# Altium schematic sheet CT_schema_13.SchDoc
size 390 x 385 mm
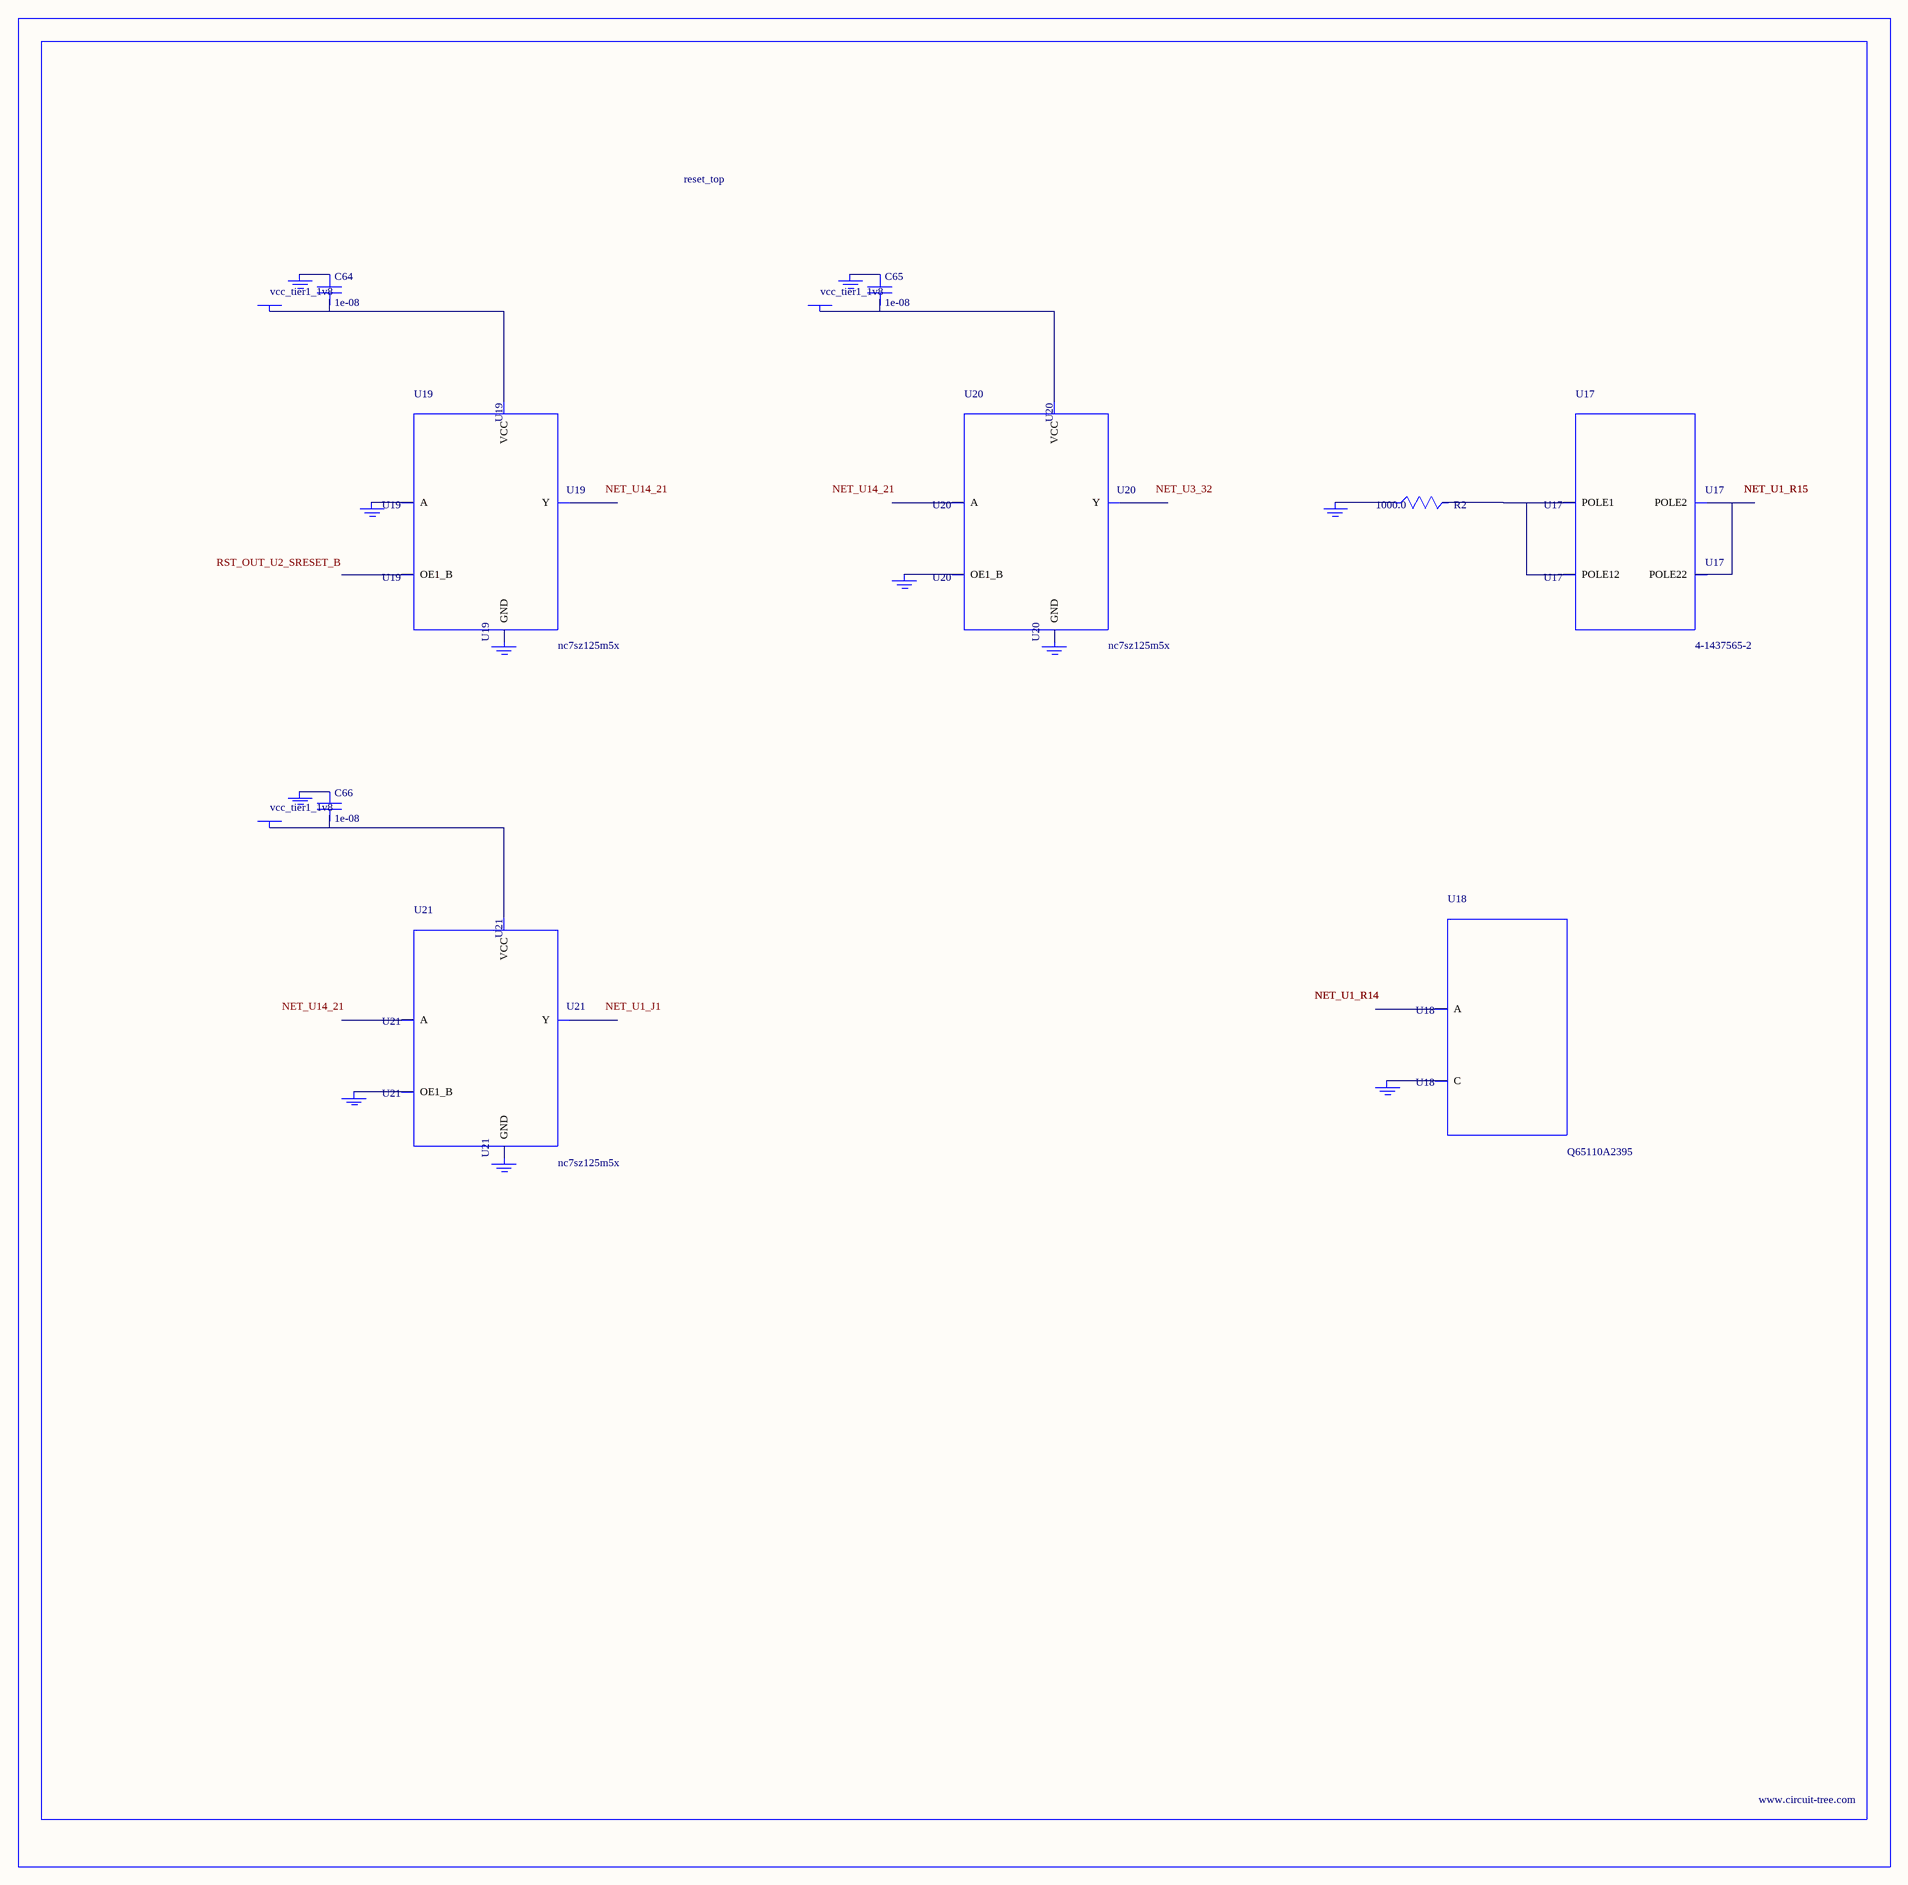
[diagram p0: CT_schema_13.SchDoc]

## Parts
BORDER12  (no value)
C64  1e-08  [C0402]
C65  1e-08  [C0402]
C66  1e-08  [C0402]
GND_INSTANCE_12_0  (no value)
GND_INSTANCE_12_1  (no value)
GND_INSTANCE_12_2  (no value)
GND_INSTANCE_12_3  (no value)
GND_INSTANCE_12_4  (no value)
GND_INSTANCE_12_5  (no value)
GND_INSTANCE_12_6  (no value)
GND_INSTANCE_12_7  (no value)
GND_INSTANCE_12_8  (no value)
GND_INSTANCE_12_9  (no value)
GND_INSTANCE_12_10  (no value)
POWER_INSTANCE_12_0  vcc_tier1_1v8
POWER_INSTANCE_12_1  vcc_tier1_1v8
POWER_INSTANCE_12_2  vcc_tier1_1v8
R2  1000.0  [R0603]
U17  4-1437565-2  [SW_4-1437565-2]
U18  Q65110A2395  [LGM67K-G1J2-24-Z]
U19  nc7sz125m5x  [NC7SZ125M5X]
U20  nc7sz125m5x  [NC7SZ125M5X]
U21  nc7sz125m5x  [NC7SZ125M5X]

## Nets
NetC64_1: C64.1 GND_INSTANCE_12_2.0(GND)
NetC64_2: C64.2 POWER_INSTANCE_12_0.0(PWR) U19.5(VCC)
NetC65_1: C65.1 GND_INSTANCE_12_5.0(GND)
NetC65_2: C65.2 POWER_INSTANCE_12_1.0(PWR) U20.5(VCC)
NetC66_1: C66.1 GND_INSTANCE_12_8.0(GND)
NetC66_2: C66.2 POWER_INSTANCE_12_2.0(PWR) U21.5(VCC)
NetGND_INSTANCE_12_0_0: GND_INSTANCE_12_0.0(GND) R2.1
NetGND_INSTANCE_12_1_0: GND_INSTANCE_12_1.0(GND) U18.C
NetGND_INSTANCE_12_3_0: GND_INSTANCE_12_3.0(GND) U19.2(A)
NetGND_INSTANCE_12_4_0: GND_INSTANCE_12_4.0(GND) U19.3(GND)
NetGND_INSTANCE_12_6_0: GND_INSTANCE_12_6.0(GND) U20.1(OE1_B)
NetGND_INSTANCE_12_7_0: GND_INSTANCE_12_7.0(GND) U20.3(GND)
NetGND_INSTANCE_12_9_0: GND_INSTANCE_12_9.0(GND) U21.1(OE1_B)
NetGND_INSTANCE_12_10_0: GND_INSTANCE_12_10.0(GND) U21.3(GND)
NetR2_2: R2.2 U17.1(POLE1) U17.2(POLE12)
NetU17_3: U17.3(POLE2) U17.4(POLE22)

Not connected (* = marked no-connect by the designer): U18 A; U19 1(OE1_B) 4(Y); U20 2(A) 4(Y); U21 2(A) 4(Y)

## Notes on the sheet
- Labels drawn without touching a wire or pin: NET_U1_J1, NET_U3_32, NET_U14_21, RST_OUT_U2_SRESET_B

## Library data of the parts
BORDER12 = BORDER_PAGE12
C64-C66 = C0402C103K3RAC
GND_INSTANCE_12_0-GND_INSTANCE_12_10 = GND
POWER_INSTANCE_12_0-POWER_INSTANCE_12_2 = PWR
R2 = RC0603JR-071KL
